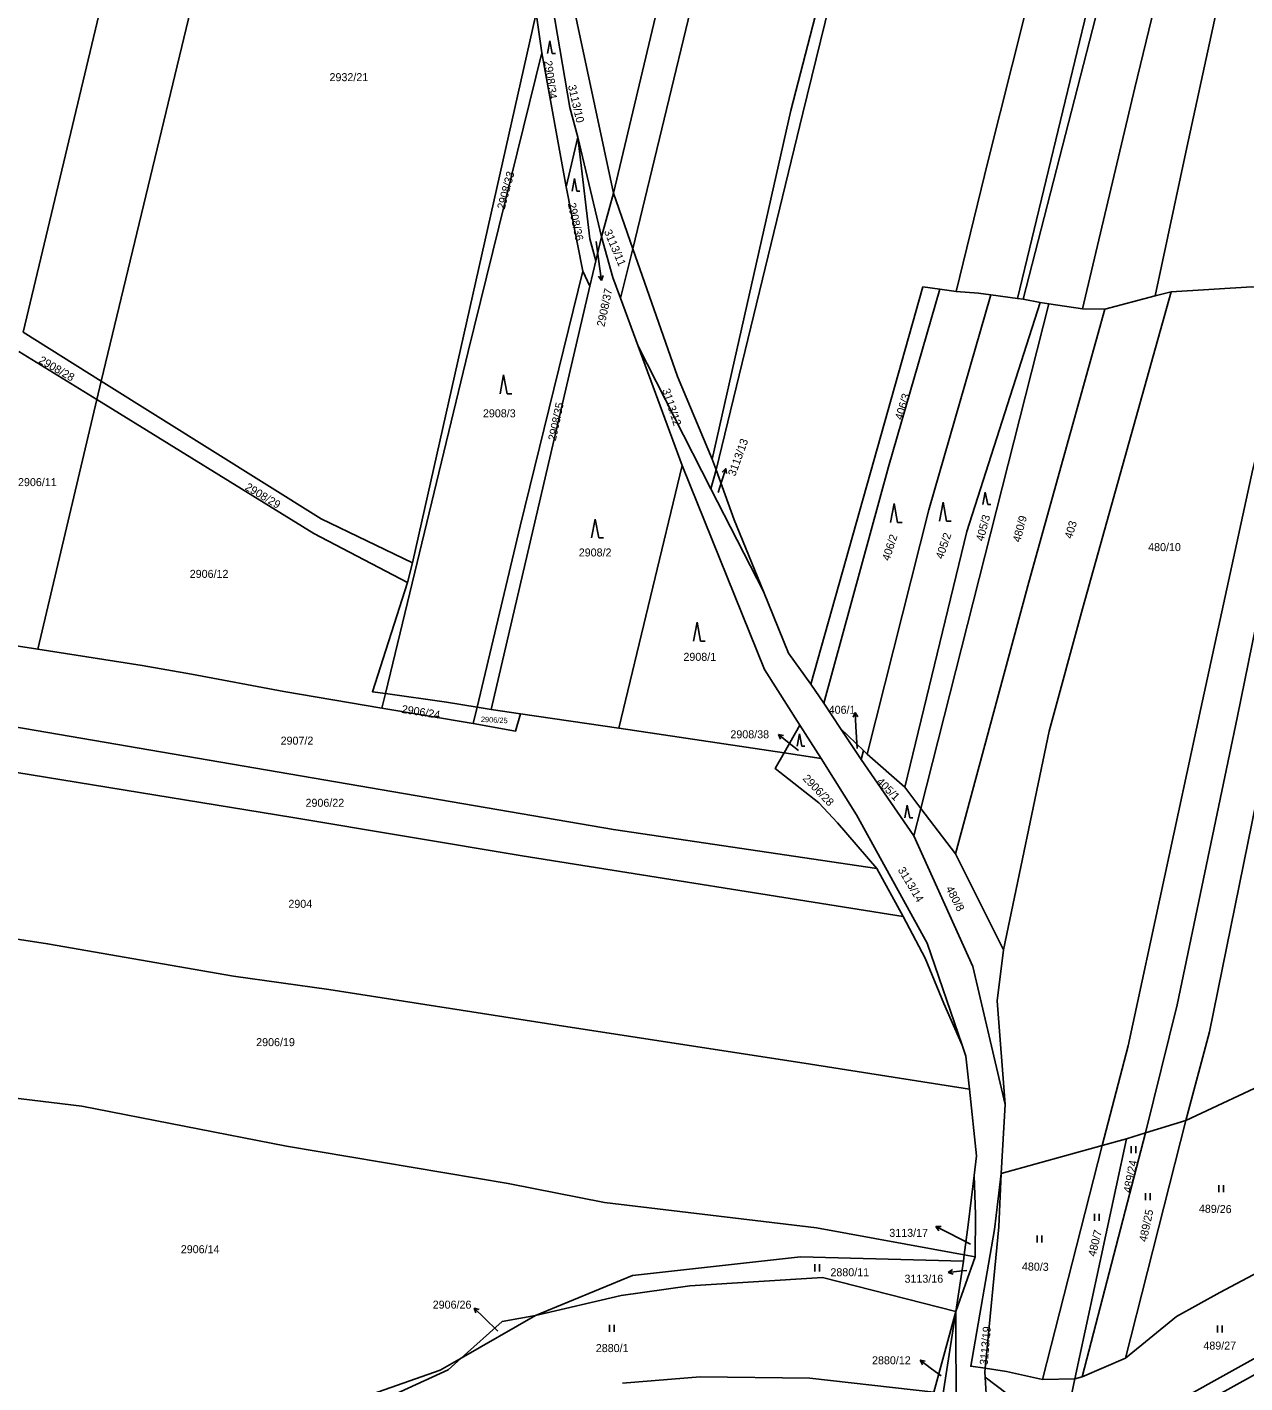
# Model space of a CAD drawing. Extents: x -776734 to -748832, y -1118122 to -976986.
# Drawn here: x -753945.5 to -753686.9, y -1114445.3 to -1114157.4 of the extents above; entities that cross this region are included whole.
import ezdxf

# ---------------------------------------------------------------- set-up
doc = ezdxf.new("R2010")
doc.units = 0
for name, color, linetype in [('KM_Hranice parcel', 7, 'Continuous'), ('KM_Parcelní čísla', 7, 'Continuous'), ('KM_Pop  PČ popisy', 7, 'Continuous'), ('KM_Značky kultur', 7, 'Continuous')]:
    doc.layers.add(name, color=color, linetype=linetype)

msp = doc.modelspace()

# ---------------------------------------------------------------- linework, layer by layer
at = {"layer": 'KM_Hranice parcel'}
for p, q in [((-753821.04, -1114192.61), (-753775.73, -1114002.11)), ((-753837.41, -1114154.43), (-753863.69, -1114271.17)), ((-753836.25, -1114162.79), (-753837.41, -1114154.43)), ((-753831.07, -1114191.28), (-753836.25, -1114162.79)), ((-753831.07, -1114191.28), (-753828.62, -1114180.76)), ((-753823.57, -1114201.91), (-753828.62, -1114180.76)), ((-753827.49, -1114209.23), (-753831.07, -1114191.28)), ((-753823.57, -1114201.91), (-753821.04, -1114192.61)), ((-753821.04, -1114192.61), (-753816.9, -1114204.45)), ((-753823.57, -1114201.91), (-753824.76, -1114207.03)), ((-753819.55, -1114214.91), (-753816.9, -1114204.45)), ((-753824.76, -1114207.03), (-753826.02, -1114212.4)), ((-753826.02, -1114212.4), (-753827.49, -1114209.23)), ((-753826.02, -1114212.4), (-753847.01, -1114302.3)), ((-753751.68, -1114213.03), (-753748.23, -1114213.51)), ((-753740.84, -1114214.22), (-753735.21, -1114215.01)), ((-753705.95, -1114214.41), (-753716.64, -1114217.28)), ((-753702.56, -1114213.59), (-753705.95, -1114214.41)), ((-753815.78, -1114225.12), (-753819.55, -1114214.91)), ((-753755.72, -1114323.3), (-753728.56, -1114216.15)), ((-753734.01, -1114215.18), (-753735.21, -1114215.01)), ((-753730.41, -1114215.82), (-753734.01, -1114215.18)), ((-753728.56, -1114216.15), (-753730.41, -1114215.82)), ((-753721.42, -1114217.18), (-753728.56, -1114216.15)), ((-753716.64, -1114217.28), (-753721.42, -1114217.18)), ((-753929.83, -1114232.54), (-753946.36, -1114222.18)), ((-753930.77, -1114236.47), (-753947.3, -1114226.28)), ((-753815.78, -1114225.12), (-753800.37, -1114255.43)), ((-753806.41, -1114250.5), (-753815.78, -1114225.12)), ((-753930.77, -1114236.47), (-753929.83, -1114232.54)), ((-753943.26, -1114289.47), (-753930.77, -1114236.47)), ((-753800.06, -1114249.13), (-753799.23, -1114251.42)), ((-753806.41, -1114250.5), (-753819.87, -1114306.3)), ((-753800.37, -1114255.43), (-753799.23, -1114251.42)), ((-753800.37, -1114255.43), (-753789.18, -1114277.25)), ((-753864.78, -1114275.33), (-753863.69, -1114271.17)), ((-753961.2, -1114286.73), (-753943.26, -1114289.47)), ((-753779.1, -1114296.9), (-753776.37, -1114300.99)), ((-753870.21, -1114302.01), (-753869.46, -1114298.92)), ((-753776.37, -1114300.99), (-753772.81, -1114306.32)), ((-753870.21, -1114302.01), (-753850.79, -1114305.28)), ((-753850.79, -1114305.28), (-753849.97, -1114301.82)), ((-753847.01, -1114302.3), (-753849.97, -1114301.82)), ((-753847.01, -1114302.3), (-753840.79, -1114303.22)), ((-753840.79, -1114303.22), (-753819.87, -1114306.3)), ((-753819.87, -1114306.3), (-753784.77, -1114311.54)), ((-753784.77, -1114311.54), (-753781.42, -1114305.64)), ((-753776.94, -1114312.71), (-753781.42, -1114305.64)), ((-753767.92, -1114311.02), (-753772.81, -1114306.32)), ((-753772.81, -1114306.32), (-753768.4, -1114312.94)), ((-753776.94, -1114312.71), (-753784.77, -1114311.54)), ((-753767.92, -1114311.02), (-753768.4, -1114312.94)), ((-753767.14, -1114311.77), (-753767.92, -1114311.02)), ((-753759.14, -1114318.8), (-753767.14, -1114311.77)), ((-753768.4, -1114312.94), (-753757.2, -1114329.14)), ((-753755.72, -1114323.3), (-753759.14, -1114318.8)), ((-753757.2, -1114329.14), (-753755.72, -1114323.3)), ((-753748.37, -1114332.97), (-753755.72, -1114323.3)), ((-753748.37, -1114332.97), (-753738.15, -1114353.35)), ((-753759.52, -1114346.27), (-753765.07, -1114336.1)), ((-753699.45, -1114389.58), (-753674.18, -1114377.77)), ((-753737.81, -1114386.24), (-753738.67, -1114400.84)), ((-753712.28, -1114440.09), (-753699.45, -1114389.58)), ((-753708, -1114392.25), (-753699.45, -1114389.58)), ((-753721.5, -1114444.02), (-753708, -1114392.25)), ((-753712.09, -1114393.53), (-753708, -1114392.25)), ((-753717.22, -1114394.94), (-753738.67, -1114400.84)), ((-753729.89, -1114444.6), (-753717.22, -1114394.94)), ((-753723.02, -1114444.48), (-753712.09, -1114393.53)), ((-753712.09, -1114393.53), (-753717.22, -1114394.94)), ((-753744.18, -1114418.58), (-753748.32, -1114430.2)), ((-753746.68, -1114419.46), (-753746.51, -1114418.17)), ((-753744.18, -1114418.58), (-753746.51, -1114418.17)), ((-753748.32, -1114430.2), (-753746.68, -1114419.46)), ((-753752.95, -1114447.28), (-753748.32, -1114430.2)), ((-753750.96, -1114447.5), (-753748.32, -1114430.2)), ((-753837.57, -1114431.02), (-753853.36, -1114440.1)), ((-753721.5, -1114444.02), (-753712.28, -1114440.09)), ((-753732.73, -1114451.24), (-753742.09, -1114444.11)), ((-753723.02, -1114444.48), (-753729.89, -1114444.6)), ((-753724.33, -1114450.59), (-753723.02, -1114444.48)), ((-753723.02, -1114444.48), (-753721.5, -1114444.02))]:
    msp.add_line(p, q, dxfattribs=at)
for points in [[(-753946.36, -1114222.18), (-753926.58, -1114139.03), (-753908.83, -1114065.02), (-753894.06, -1114004.7), (-753890.46, -1113981.25)], [(-753721.42, -1114217.18), (-753710.28, -1114170.24), (-753684.76, -1114064.89), (-753667.83, -1113993.57)], [(-753929.83, -1114232.54), (-753901.82, -1114116.18), (-753883.15, -1114038.26), (-753873.96, -1114002.11)], [(-753768, -1114002.15), (-753779.81, -1114052.73), (-753797.44, -1114123.84), (-753816.9, -1114204.45)], [(-753800.06, -1114249.13), (-753783.35, -1114175.05), (-753748.32, -1114039.61)], [(-753748.32, -1114039.61), (-753766.62, -1114117.83), (-753780.82, -1114175.62), (-753799.23, -1114251.42)], [(-753705.95, -1114214.41), (-753699.25, -1114182.95), (-753683.03, -1114108.23), (-753669.63, -1114046.38)], [(-753708.31, -1114054.03), (-753741.47, -1114185.71), (-753748.23, -1114213.51)], [(-753735.21, -1114215.01), (-753719.99, -1114151.98), (-753708.89, -1114107.17), (-753696.25, -1114055.07)], [(-753734.01, -1114215.18), (-753692.96, -1114055.35), (-753696.25, -1114055.07)], [(-753831.54, -1114142.69), (-753830.7, -1114147.21), (-753821.04, -1114192.61)], [(-753828.62, -1114180.76), (-753830.25, -1114174.42), (-753833.96, -1114152.83)], [(-753836.25, -1114162.79), (-753851.87, -1114226.24), (-753869.46, -1114298.92)], [(-753824.76, -1114207.03), (-753826.04, -1114202.33), (-753828.62, -1114180.76)], [(-753819.55, -1114214.91), (-753821.17, -1114210.53), (-753823.57, -1114201.91)], [(-753816.9, -1114204.45), (-753807.4, -1114231.59), (-753800.06, -1114249.13)], [(-753659, -1114206.7), (-753667.62, -1114242.75), (-753671.74, -1114263.06), (-753681.78, -1114308.41), (-753694.46, -1114370.79), (-753699.45, -1114389.58)], [(-753849.97, -1114301.82), (-753840.81, -1114263.36), (-753827.49, -1114209.23)], [(-753708, -1114392.25), (-753701.28, -1114365.01), (-753688.54, -1114304.06), (-753678.05, -1114252.61), (-753667.82, -1114209.75)], [(-753779.1, -1114296.9), (-753755.31, -1114212.53), (-753751.68, -1114213.03)], [(-753751.68, -1114213.03), (-753762.6, -1114250.78), (-753776.37, -1114300.99)], [(-753740.84, -1114214.22), (-753754.01, -1114259.88), (-753767.14, -1114311.77)], [(-753748.23, -1114213.51), (-753743.51, -1114213.84), (-753740.84, -1114214.22)], [(-753738.15, -1114353.35), (-753728.49, -1114306.9), (-753721.4, -1114280.95), (-753702.56, -1114213.59)], [(-753717.22, -1114394.94), (-753711.71, -1114373.72), (-753696.26, -1114302.1), (-753685.2, -1114251.27), (-753680.42, -1114232.21), (-753675.9, -1114212.89)], [(-753675.9, -1114212.89), (-753685.42, -1114212.53), (-753702.56, -1114213.59)], [(-753759.14, -1114318.8), (-753745.94, -1114264.49), (-753730.41, -1114215.82)], [(-753716.64, -1114217.28), (-753732.77, -1114275.26), (-753748.37, -1114332.97)], [(-753863.69, -1114271.17), (-753883.1, -1114261.82), (-753929.83, -1114232.54)], [(-753864.78, -1114275.33), (-753884.63, -1114264.92), (-753930.77, -1114236.47)], [(-753781.42, -1114305.64), (-753788.92, -1114293.81), (-753806.41, -1114250.5)], [(-753799.23, -1114251.42), (-753795.36, -1114262.04), (-753789.18, -1114277.25)], [(-753869.46, -1114298.92), (-753872.22, -1114298.52), (-753864.78, -1114275.33)], [(-753789.18, -1114277.25), (-753783.85, -1114290.36), (-753779.1, -1114296.9)], [(-753943.26, -1114289.47), (-753921.14, -1114292.98), (-753910.62, -1114294.83), (-753891, -1114298.47), (-753870.21, -1114302.01)], [(-753765.07, -1114336.1), (-753821.03, -1114327.8), (-753975.91, -1114301.21), (-754030.89, -1114290.27)], [(-753759.52, -1114346.27), (-753840.42, -1114333.36), (-753889.11, -1114325.26), (-753964.29, -1114313.02), (-753978.31, -1114310.42), (-754031.35, -1114299.67)], [(-753869.46, -1114298.92), (-753856.47, -1114300.78), (-753849.97, -1114301.82)], [(-753850.79, -1114305.28), (-753841.8, -1114306.88), (-753840.79, -1114303.22)], [(-753784.77, -1114311.54), (-753786.64, -1114314.84), (-753777.37, -1114322.12), (-753773.44, -1114326.41), (-753765.07, -1114336.1)], [(-753746.95, -1114373.64), (-753754.36, -1114351.92), (-753769.42, -1114324.68), (-753776.94, -1114312.71)], [(-753757.2, -1114329.14), (-753744.68, -1114356.91), (-753737.81, -1114386.24)], [(-754030.43, -1114340.22), (-754009.35, -1114341.58), (-753941.21, -1114352.06), (-753901.7, -1114358.94), (-753881.46, -1114361.76), (-753833, -1114369.38), (-753779.2, -1114377.65), (-753745.43, -1114382.97)], [(-753746.95, -1114373.64), (-753750.82, -1114364.78), (-753754.8, -1114355.12), (-753759.52, -1114346.27)], [(-753737.81, -1114386.24), (-753739.55, -1114364.18), (-753738.15, -1114353.35)], [(-753745.43, -1114382.97), (-753746.18, -1114375.91), (-753746.95, -1114373.64)], [(-753746.51, -1114418.17), (-753777.92, -1114412.38), (-753822.95, -1114406.99), (-753843.35, -1114402.99), (-753890.43, -1114395.08), (-753933.9, -1114386.59), (-753983.18, -1114380.59), (-754026.51, -1114379.02)], [(-753744.43, -1114401.26), (-753743.94, -1114397.09), (-753745.43, -1114382.97)], [(-753746.51, -1114418.17), (-753745.68, -1114411.77), (-753744.43, -1114401.26)], [(-753742.07, -1114442.2), (-753745.14, -1114441.79), (-753740.09, -1114412.74), (-753738.67, -1114400.84)], [(-753744.43, -1114401.26), (-753744.11, -1114409.58), (-753744.18, -1114418.58)], [(-753738.67, -1114400.84), (-753739.14, -1114412.18), (-753742.07, -1114442.2)], [(-753746.68, -1114419.46), (-753781.28, -1114418.59), (-753816.96, -1114422.51), (-753837.57, -1114431.02)], [(-753712.28, -1114440.09), (-753701.41, -1114431.22), (-753692.24, -1114426.15), (-753682.86, -1114421.22)], [(-753748.32, -1114430.2), (-753776.63, -1114422.99), (-753804.83, -1114424.76), (-753819.37, -1114426.81), (-753837.57, -1114431.02)], [(-753748.32, -1114430.2), (-753748.22, -1114452.41), (-753744.57, -1114461.02)], [(-753853.36, -1114440.1), (-753844.69, -1114432.32), (-753837.57, -1114431.02)], [(-753675.09, -1114433.62), (-753678.94, -1114436.81), (-753700.91, -1114449.06), (-753724.33, -1114450.59)], [(-753727.51, -1114455.22), (-753701.13, -1114452.61), (-753681.36, -1114441.65), (-753676.94, -1114438.64)], [(-753853.36, -1114440.1), (-753857.8, -1114442.65), (-753899.76, -1114457.35)], [(-753853.36, -1114440.1), (-753856.15, -1114442.6), (-753871.41, -1114449.57)], [(-753742.07, -1114442.2), (-753742.15, -1114443.03), (-753742.09, -1114444.11)], [(-753742.07, -1114442.2), (-753737.56, -1114442.95), (-753729.89, -1114444.6)], [(-753819.09, -1114445.4), (-753802.6, -1114444.02), (-753779.31, -1114444.37), (-753752.95, -1114447.28)], [(-753742.09, -1114444.11), (-753741.75, -1114450.1), (-753740.87, -1114451.87)]]:
    msp.add_lwpolyline(points, dxfattribs=at)
at = {"layer": 'KM_Pop  PČ popisy'}
for p, q in [((-753824.66, -1114202.91), (-753823.96, -1114208.23)), ((-753823.96, -1114208.23), (-753823.542, -1114211.202)), ((-753823.542, -1114211.202), (-753824.178, -1114210.28)), ((-753823.542, -1114211.202), (-753823.186, -1114210.14)), ((-753798.06, -1114253.96), (-753797.183, -1114251.09)), ((-753797.183, -1114251.09), (-753797.954, -1114251.901)), ((-753797.183, -1114251.09), (-753796.997, -1114252.194)), ((-753798.77, -1114256.23), (-753798.06, -1114253.96)), ((-753769.687, -1114302.923), (-753770.135, -1114303.949)), ((-753769.53, -1114305.92), (-753769.687, -1114302.923)), ((-753769.687, -1114302.923), (-753769.135, -1114303.897)), ((-753769.28, -1114310.61), (-753769.53, -1114305.92)), ((-753783.67, -1114309.47), (-753786.002, -1114307.581)), ((-753786.002, -1114307.581), (-753784.909, -1114307.823)), ((-753786.002, -1114307.581), (-753785.539, -1114308.601)), ((-753781.75, -1114311.03), (-753783.67, -1114309.47)), ((-753749.89, -1114413.49), (-753752.564, -1114412.128)), ((-753752.564, -1114412.128), (-753751.444, -1114412.136)), ((-753752.564, -1114412.128), (-753751.899, -1114413.028)), ((-753745.21, -1114415.86), (-753749.89, -1114413.49)), ((-753749.935, -1114421.864), (-753748.991, -1114421.261)), ((-753746.95, -1114421.55), (-753749.935, -1114421.864)), ((-753749.935, -1114421.864), (-753748.886, -1114422.257)), ((-753745.99, -1114421.45), (-753746.95, -1114421.55)), ((-753848.46, -1114431.52), (-753850.619, -1114429.435)), ((-753850.619, -1114429.435), (-753849.55, -1114429.771)), ((-753850.619, -1114429.435), (-753850.246, -1114430.491)), ((-753845.56, -1114434.33), (-753848.46, -1114431.52)), ((-753753.5, -1114442.33), (-753755.897, -1114440.524)), ((-753755.897, -1114440.524), (-753754.796, -1114440.727)), ((-753755.897, -1114440.524), (-753755.398, -1114441.527)), ((-753751.44, -1114443.85), (-753753.5, -1114442.33))]:
    msp.add_line(p, q, dxfattribs=at)
at = {"layer": 'KM_Značky kultur'}
for p, q in [((-753834.51, -1114160.29), (-753835.012, -1114162.97)), ((-753834.008, -1114162.97), (-753834.51, -1114160.29)), ((-753834.008, -1114162.97), (-753833.34, -1114162.97)), ((-753829.31, -1114189.51), (-753829.812, -1114192.19)), ((-753828.808, -1114192.19), (-753829.31, -1114189.51)), ((-753828.808, -1114192.19), (-753828.14, -1114192.19)), ((-753844.35, -1114231.23), (-753845.1, -1114235.23)), ((-753843.6, -1114235.23), (-753844.35, -1114231.23)), ((-753843.6, -1114235.23), (-753842.604, -1114235.23)), ((-753742.04, -1114256.11), (-753742.542, -1114258.79)), ((-753741.538, -1114258.79), (-753742.04, -1114256.11)), ((-753761.43, -1114258.56), (-753762.18, -1114262.56)), ((-753760.68, -1114262.56), (-753761.43, -1114258.56)), ((-753751.02, -1114258.3), (-753751.77, -1114262.3)), ((-753750.27, -1114262.3), (-753751.02, -1114258.3)), ((-753741.538, -1114258.79), (-753740.87, -1114258.79)), ((-753824.91, -1114261.86), (-753825.66, -1114265.86)), ((-753824.16, -1114265.86), (-753824.91, -1114261.86)), ((-753760.68, -1114262.56), (-753759.684, -1114262.56)), ((-753750.27, -1114262.3), (-753749.274, -1114262.3)), ((-753824.16, -1114265.86), (-753823.164, -1114265.86)), ((-753803.27, -1114283.79), (-753804.02, -1114287.79)), ((-753802.52, -1114287.79), (-753803.27, -1114283.79)), ((-753802.52, -1114287.79), (-753801.524, -1114287.79)), ((-753781.51, -1114307.44), (-753782.012, -1114310.12)), ((-753781.008, -1114310.12), (-753781.51, -1114307.44)), ((-753781.008, -1114310.12), (-753780.34, -1114310.12)), ((-753758.61, -1114322.64), (-753759.112, -1114325.32)), ((-753758.108, -1114325.32), (-753758.61, -1114322.64)), ((-753758.108, -1114325.32), (-753757.44, -1114325.32)), ((-753711.061, -1114396.53), (-753711.061, -1114395.03)), ((-753710.06, -1114396.53), (-753710.06, -1114395.03)), ((-753692.471, -1114404.86), (-753692.471, -1114403.36)), ((-753691.47, -1114404.86), (-753691.47, -1114403.36)), ((-753708.001, -1114406.53), (-753708.001, -1114405.03)), ((-753707, -1114406.53), (-753707, -1114405.03)), ((-753718.861, -1114410.95), (-753718.861, -1114409.45)), ((-753717.86, -1114410.95), (-753717.86, -1114409.45)), ((-753731.041, -1114415.5), (-753731.041, -1114414)), ((-753730.04, -1114415.5), (-753730.04, -1114414)), ((-753778.251, -1114421.65), (-753778.251, -1114420.15)), ((-753777.25, -1114421.65), (-753777.25, -1114420.15)), ((-753821.851, -1114434.52), (-753821.851, -1114433.02)), ((-753820.85, -1114434.52), (-753820.85, -1114433.02)), ((-753692.741, -1114434.62), (-753692.741, -1114433.12)), ((-753691.74, -1114434.62), (-753691.74, -1114433.12))]:
    msp.add_line(p, q, dxfattribs=at)

# ---------------------------------------------------------------- texts
at = {"layer": 'KM_Parcelní čísla'}
for s, height, rotation, p in [('2908/34', 1.7, 278, (-753835.761, -1114164.578)), ('3113/10', 1.7, 283, (-753830.688, -1114169.811)), ('2908/33', 1.7, 75, (-753844.138, -1114196.209)), ('2908/36', 1.7, 282, (-753830.721, -1114194.856)), ('3113/11', 1.7, 293, (-753823.072, -1114200.762)), ('2908/37', 1.7, 78, (-753822.944, -1114221.113)), ('2908/28', 1.7, 329.999997, (-753943.235, -1114228.576)), ('3113/12', 1.7, 288, (-753810.708, -1114234.422)), ('2908/35', 1.7, 78, (-753833.268, -1114245.326)), ('406/3', 1.7, 73, (-753759.677, -1114240.938)), ('3113/13', 1.7, 70, (-753795.173, -1114252.89)), ('2908/29', 1.7, 329, (-753899.427, -1114255.498)), ('405/3', 1.7, 75, (-753742.448, -1114266.699)), ('480/9', 1.7, 75, (-753734.638, -1114266.889)), ('403', 1.7, 73, (-753723.657, -1114266.168)), ('406/2', 1.7, 72, (-753762.421, -1114270.842)), ('405/2', 1.7, 71, (-753751.066, -1114270.486)), ('2906/24', 1.7, 351, (-753866.092, -1114303.009)), ('2906/25', 1.14, 357, (-753849.198, -1114304.937)), ('2906/28', 1.7, 313.999997, (-753780.951, -1114317.08)), ('405/1', 1.7, 315, (-753765.261, -1114317.791)), ('3113/14', 1.7, 301, (-753760.698, -1114336.377)), ('480/8', 1.7, 297, (-753750.487, -1114340.315)), ('489/24', 1.7, 79, (-753711.105, -1114405.052)), ('489/26', 1.7, 359, (-753696.694, -1114409.169)), ('489/25', 1.7, 78, (-753707.778, -1114415.486)), ('480/7', 1.7, 76, (-753718.635, -1114418.615)), ('480/3', 1.7, 359, (-753734.284, -1114421.449)), ('3113/19', 1.7, 85, (-753741.563, -1114441.614))]:
    msp.add_text(s, height=height, rotation=rotation, dxfattribs=at).set_placement(p)
for s, p in [('2932/21', (-753881.32, -1114168.84)), ('2908/3', (-753848.74, -1114240.24)), ('2906/11', (-753947.48, -1114254.86)), ('2908/2', (-753828.39, -1114269.8)), ('480/10', (-753707.46, -1114268.66)), ('2906/12', (-753911.01, -1114274.35)), ('2908/1', (-753806.16, -1114291.97)), ('406/1', (-753775.307, -1114303.21)), ('2908/38', (-753796.183, -1114308.42)), ('2907/2', (-753891.71, -1114309.77)), ('2906/22', (-753886.42, -1114322.97)), ('2904', (-753890.06, -1114344.43)), ('2906/19', (-753896.9, -1114373.81)), ('3113/17', (-753762.433, -1114414.32)), ('2906/14', (-753912.91, -1114417.8)), ('2880/11', (-753774.94, -1114422.69)), ('3113/16', (-753759.206, -1114424.06)), ('2906/26', (-753859.403, -1114429.57)), ('489/27', (-753695.73, -1114438.27)), ('2880/1', (-753824.77, -1114438.8)), ('2880/12', (-753766.103, -1114441.39))]:
    msp.add_text(s, height=1.7, dxfattribs=at).set_placement(p)

doc.saveas('drawing.dxf')
